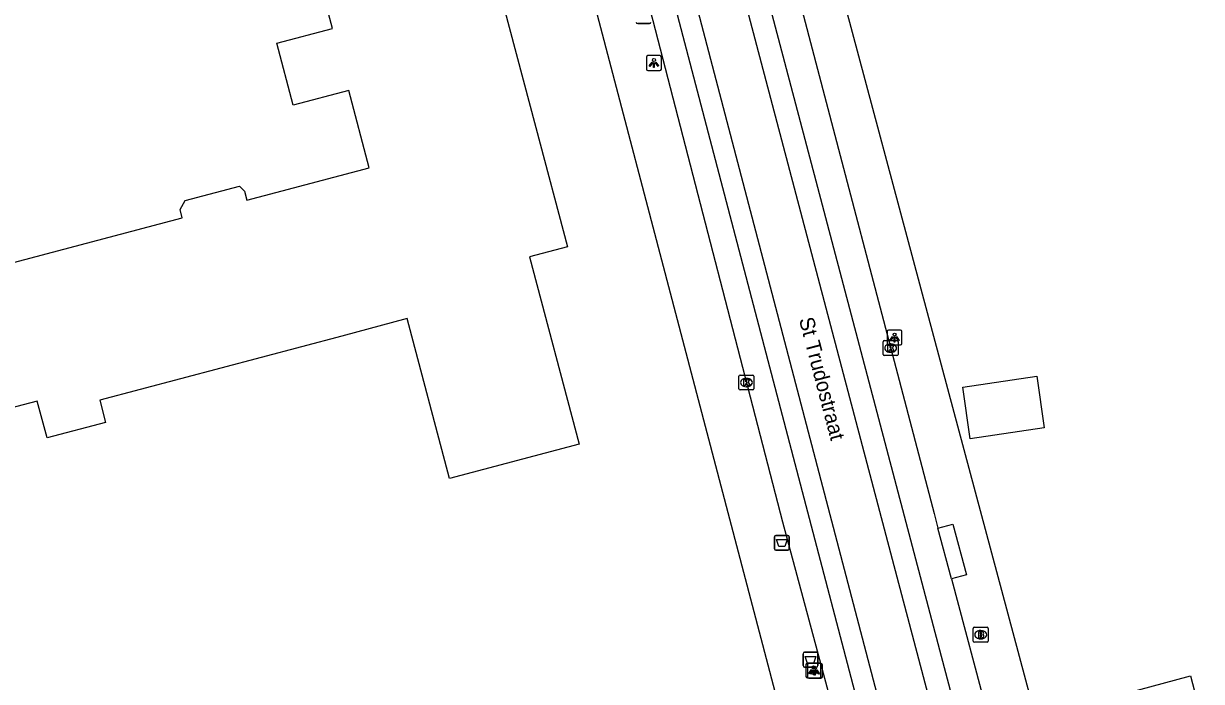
# Model space of a CAD drawing. Extents: x 159377 to 159983, y 382996 to 383595.
# Drawn here: x 159627.9 to 159706.9, y 383388.8 to 383433 of the extents above; entities that cross this region are included whole.
import ezdxf

# ---------------------------------------------------------------- set-up
doc = ezdxf.new("R2010")
doc.units = 0
for name, color, linetype in [('IMGEO_Afvalbak', 7, 'Continuous'), ('IMGEO_Brandkraan', 7, 'Continuous'), ('IMGEO_Kolk', 7, 'Continuous'), ('IMGEO_Lichtpunt', 7, 'Continuous'), ('IMGEO_Openbare_ruimte_label', 7, 'Continuous'), ('IMGEO_Pand', 7, 'Continuous'), ('IMGEO_Rijbaan_lokaal_gesloten', 7, 'Continuous'), ('IMGEO_Voetpad_open', 7, 'Continuous')]:
    doc.layers.add(name, color=color, linetype=linetype)

msp = doc.modelspace()

# ---------------------------------------------------------------- linework, layer by layer
at = {"layer": 'IMGEO_Afvalbak'}
for p, q in [((159669.861, 383432.991), (159669.071, 383432.991)), ((159669.071, 383432.991), (159669.861, 383432.991)), ((159678.253, 383397.748), (159678.253, 383398.548)), ((159678.253, 383398.548), (159678.253, 383397.748)), ((159678.353, 383398.648), (159679.143, 383398.648)), ((159679.143, 383398.648), (159678.353, 383398.648)), ((159679.243, 383398.548), (159679.243, 383397.748)), ((159679.243, 383397.748), (159679.243, 383398.548)), ((159679.143, 383397.648), (159678.353, 383397.648)), ((159678.353, 383397.648), (159679.143, 383397.648)), ((159680.176, 383389.909), (159680.176, 383390.709)), ((159680.176, 383390.709), (159680.176, 383389.909)), ((159680.276, 383390.809), (159681.066, 383390.809)), ((159681.066, 383390.809), (159680.276, 383390.809)), ((159681.166, 383390.709), (159681.166, 383389.909)), ((159681.166, 383389.909), (159681.166, 383390.709)), ((159681.066, 383389.809), (159680.276, 383389.809)), ((159680.276, 383389.809), (159681.066, 383389.809))]:
    msp.add_line(p, q, dxfattribs=at)
for points in [[(159678.396, 383398.362), (159679.1, 383398.362), (159678.951, 383397.892), (159678.545, 383397.892), (159678.396, 383398.362)], [(159680.319, 383390.523), (159681.023, 383390.523), (159680.874, 383390.053), (159680.468, 383390.053), (159680.319, 383390.523)]]:
    msp.add_lwpolyline(points, dxfattribs=at)
for centre, start, end in [((159669.071, 383433.091), 180, 270), ((159669.071, 383433.091), 180, 270), ((159669.861, 383433.091), 270, 0), ((159669.861, 383433.091), 270, 0), ((159678.353, 383398.548), 90, 180), ((159678.353, 383398.548), 90, 180), ((159679.143, 383398.548), 0, 90), ((159679.143, 383398.548), 360, 90), ((159678.353, 383397.748), 180, 270), ((159678.353, 383397.748), 180, 270), ((159679.143, 383397.748), 270, 0), ((159679.143, 383397.748), 270, 0), ((159680.276, 383390.709), 90, 180), ((159680.276, 383390.709), 90, 180), ((159681.066, 383390.709), 0, 90), ((159681.066, 383390.709), 360, 90), ((159680.276, 383389.909), 180, 270), ((159680.276, 383389.909), 180, 270), ((159681.066, 383389.909), 270, 0), ((159681.066, 383389.909), 270, 0)]:
    msp.add_arc(centre, 0.1, start, end, dxfattribs=at)
at = {"layer": 'IMGEO_Brandkraan'}
for p, q in [((159691.594, 383391.559), (159691.594, 383392.411)), ((159691.669, 383392.485), (159692.521, 383392.485)), ((159692.082, 383392.265), (159692.107, 383392.265)), ((159692.595, 383392.411), (159692.595, 383391.559)), ((159692.521, 383391.485), (159691.669, 383391.485)), ((159692.105, 383391.705), (159692.08, 383391.705))]:
    msp.add_line(p, q, dxfattribs=at)
for points in [[(159691.594, 383391.559), (159691.594, 383392.411)], [(159691.669, 383392.485), (159692.521, 383392.485)], [(159691.942, 383392.185), (159691.942, 383391.785), (159692.155, 383391.785)], [(159692.173, 383392.185), (159691.942, 383392.185)], [(159692.121, 383392.104), (159692.067, 383392.104), (159692.067, 383392.028)], [(159692.067, 383392.028), (159692.12, 383392.028)], [(159692.129, 383391.952), (159692.067, 383391.952), (159692.067, 383391.871)], [(159692.067, 383391.871), (159692.129, 383391.871)], [(159692.595, 383392.411), (159692.595, 383391.559)], [(159692.521, 383391.485), (159691.669, 383391.485)]]:
    msp.add_lwpolyline(points, dxfattribs=at)
for centre, radius, start, end in [((159691.671, 383392.409), 0.0765, 91.55205, 178.44795), ((159691.671, 383392.409), 0.0765, 91.55205, 178.44795), ((159692.122, 383392.066), 0.0379, 267.82845, 90.93552), ((159692.13, 383391.911), 0.0404, 269.87594, 90.50774), ((159692.161, 383392.036), 0.251, 268.66757, 293.53466), ((159692.177, 383392.04), 0.145, 59.4692, 91.53667), ((159692.202, 383392.087), 0.0922, 285.51372, 58.15012), ((159692.207, 383391.895), 0.105, 301.31148, 78.98903), ((159692.519, 383392.409), 0.0765, 1.55205, 88.44795), ((159692.519, 383392.409), 0.0765, 1.55205, 88.44795), ((159691.671, 383391.561), 0.0765, 181.55205, 268.44795), ((159691.671, 383391.561), 0.0765, 181.55205, 268.44795), ((159692.519, 383391.561), 0.0765, 271.55205, 358.44795), ((159692.519, 383391.561), 0.0765, 271.55205, 358.44795)]:
    msp.add_arc(centre, radius, start, end, dxfattribs=at)
for centre, major_axis, ratio, start_param, end_param in [((159692.081, 383391.985), (-0.387, 0.002), 0.722429, 4.712389, 7.853982), ((159692.106, 383391.985), (-0.39, 0.002), 0.717154, 1.570796, 4.712389)]:
    msp.add_ellipse(centre, major_axis=major_axis, ratio=ratio, start_param=start_param, end_param=end_param, dxfattribs=at)
at = {"layer": 'IMGEO_Kolk'}
for p, q in [((159685.548, 383410.789), (159685.548, 383411.641)), ((159685.623, 383411.715), (159686.475, 383411.715)), ((159686.036, 383411.495), (159686.061, 383411.495)), ((159686.549, 383411.641), (159686.549, 383410.789)), ((159686.475, 383410.715), (159685.623, 383410.715)), ((159686.059, 383410.935), (159686.034, 383410.935)), ((159675.871, 383408.48), (159675.871, 383409.332)), ((159675.946, 383409.406), (159676.798, 383409.406)), ((159676.359, 383409.186), (159676.384, 383409.186)), ((159676.872, 383409.332), (159676.872, 383408.48)), ((159676.798, 383408.406), (159675.946, 383408.406)), ((159676.382, 383408.626), (159676.357, 383408.626))]:
    msp.add_line(p, q, dxfattribs=at)
for points in [[(159685.548, 383410.789), (159685.548, 383411.641)], [(159685.623, 383411.715), (159686.475, 383411.715)], [(159686.549, 383411.641), (159686.549, 383410.789)], [(159686.475, 383410.715), (159685.623, 383410.715)], [(159685.869, 383411.415), (159685.992, 383411.415), (159685.992, 383411.264), (159686.122, 383411.415), (159686.286, 383411.415), (159686.14, 383411.264), (159686.293, 383411.015), (159686.141, 383411.015), (159686.056, 383411.179), (159685.992, 383411.112), (159685.992, 383411.015), (159685.869, 383411.015), (159685.869, 383411.415)], [(159675.871, 383408.48), (159675.871, 383409.332)], [(159675.946, 383409.406), (159676.798, 383409.406)], [(159676.192, 383409.106), (159676.315, 383409.106), (159676.315, 383408.955), (159676.445, 383409.106), (159676.609, 383409.106), (159676.463, 383408.955), (159676.616, 383408.706), (159676.464, 383408.706), (159676.379, 383408.87), (159676.315, 383408.803), (159676.315, 383408.706), (159676.192, 383408.706), (159676.192, 383409.106)], [(159676.872, 383409.332), (159676.872, 383408.48)], [(159676.798, 383408.406), (159675.946, 383408.406)]]:
    msp.add_lwpolyline(points, dxfattribs=at)
for centre, start, end in [((159685.625, 383411.639), 91.55205, 178.44795), ((159685.625, 383411.639), 91.55205, 178.44795), ((159686.473, 383411.639), 1.55205, 88.44795), ((159686.473, 383411.639), 1.55205, 88.44795), ((159685.625, 383410.791), 181.55205, 268.44795), ((159685.625, 383410.791), 181.55205, 268.44795), ((159686.473, 383410.791), 271.55205, 358.44795), ((159686.473, 383410.791), 271.55205, 358.44795), ((159675.948, 383409.33), 91.55205, 178.44795), ((159675.948, 383409.33), 91.55205, 178.44795), ((159676.796, 383409.33), 1.55205, 88.44795), ((159676.796, 383409.33), 1.55205, 88.44795), ((159675.948, 383408.482), 181.55205, 268.44795), ((159675.948, 383408.482), 181.55205, 268.44795), ((159676.796, 383408.482), 271.55205, 358.44795), ((159676.796, 383408.482), 271.55205, 358.44795)]:
    msp.add_arc(centre, 0.0765, start, end, dxfattribs=at)
for centre, major_axis, ratio, start_param, end_param in [((159686.035, 383411.215), (-0.387, 0.002), 0.722429, 4.712389, 7.853982), ((159686.06, 383411.215), (-0.39, 0.002), 0.717154, 1.570796, 4.712389), ((159676.358, 383408.906), (-0.387, 0.002), 0.722429, 4.712389, 7.853982), ((159676.383, 383408.906), (-0.39, 0.002), 0.717154, 1.570796, 4.712389)]:
    msp.add_ellipse(centre, major_axis=major_axis, ratio=ratio, start_param=start_param, end_param=end_param, dxfattribs=at)
at = {"layer": 'IMGEO_Lichtpunt'}
for p, q in [((159669.666, 383430.746), (159669.666, 383429.939)), ((159669.666, 383430.746), (159669.666, 383429.939)), ((159670.568, 383430.841), (159669.76, 383430.841)), ((159670.568, 383430.841), (159669.76, 383430.841)), ((159670.662, 383429.939), (159670.662, 383430.746)), ((159670.662, 383429.939), (159670.662, 383430.746)), ((159669.76, 383429.845), (159670.568, 383429.845)), ((159669.76, 383429.845), (159670.568, 383429.845)), ((159685.81, 383412.327), (159685.81, 383411.52)), ((159685.81, 383412.327), (159685.81, 383411.52)), ((159686.712, 383412.422), (159685.904, 383412.422)), ((159686.712, 383412.422), (159685.904, 383412.422)), ((159686.806, 383411.52), (159686.806, 383412.327)), ((159686.806, 383411.52), (159686.806, 383412.327)), ((159685.904, 383411.426), (159686.712, 383411.426)), ((159685.904, 383411.426), (159686.712, 383411.426)), ((159680.364, 383389.989), (159680.364, 383389.182)), ((159680.364, 383389.989), (159680.364, 383389.182)), ((159681.266, 383390.084), (159680.458, 383390.084)), ((159681.266, 383390.084), (159680.458, 383390.084)), ((159680.469, 383389.966), (159680.469, 383389.159)), ((159680.469, 383389.966), (159680.469, 383389.159)), ((159681.371, 383390.061), (159680.563, 383390.061)), ((159681.371, 383390.061), (159680.563, 383390.061)), ((159681.36, 383389.182), (159681.36, 383389.989)), ((159681.36, 383389.182), (159681.36, 383389.989)), ((159681.465, 383389.159), (159681.465, 383389.966)), ((159681.465, 383389.159), (159681.465, 383389.966)), ((159680.458, 383389.088), (159681.266, 383389.088)), ((159680.458, 383389.088), (159681.266, 383389.088)), ((159680.563, 383389.065), (159681.371, 383389.065)), ((159680.563, 383389.065), (159681.371, 383389.065))]:
    msp.add_line(p, q, dxfattribs=at)
for points in [[(159670.04, 383430.41), (159670.079, 383430.382), (159669.891, 383430.12), (159669.853, 383430.147), (159670.04, 383430.41)], [(159670.142, 383430.362), (159670.189, 383430.362), (159670.189, 383430.04), (159670.142, 383430.04), (159670.142, 383430.362)], [(159670.252, 383430.382), (159670.29, 383430.409), (159670.477, 383430.147), (159670.438, 383430.119), (159670.252, 383430.382)], [(159686.184, 383411.991), (159686.223, 383411.963), (159686.035, 383411.701), (159685.997, 383411.728), (159686.184, 383411.991)], [(159686.286, 383411.943), (159686.333, 383411.943), (159686.333, 383411.621), (159686.286, 383411.621), (159686.286, 383411.943)], [(159686.396, 383411.963), (159686.434, 383411.99), (159686.621, 383411.728), (159686.582, 383411.7), (159686.396, 383411.963)], [(159680.738, 383389.653), (159680.777, 383389.625), (159680.589, 383389.363), (159680.551, 383389.39), (159680.738, 383389.653)], [(159680.843, 383389.63), (159680.882, 383389.602), (159680.694, 383389.34), (159680.656, 383389.367), (159680.843, 383389.63)], [(159680.84, 383389.605), (159680.887, 383389.605), (159680.887, 383389.283), (159680.84, 383389.283), (159680.84, 383389.605)], [(159680.945, 383389.582), (159680.992, 383389.582), (159680.992, 383389.26), (159680.945, 383389.26), (159680.945, 383389.582)], [(159680.95, 383389.625), (159680.988, 383389.652), (159681.175, 383389.39), (159681.136, 383389.362), (159680.95, 383389.625)], [(159681.055, 383389.602), (159681.093, 383389.629), (159681.28, 383389.367), (159681.241, 383389.339), (159681.055, 383389.602)]]:
    msp.add_lwpolyline(points, dxfattribs=at)
for centre in [(159670.165, 383430.544), (159686.309, 383412.125), (159680.863, 383389.787), (159680.968, 383389.764)]:
    msp.add_circle(centre, 0.0994, dxfattribs=at)
for centre, start, end in [((159669.76, 383430.746), 90, 180), ((159669.76, 383430.746), 90, 180), ((159670.568, 383430.746), 0, 90), ((159670.568, 383430.746), 0, 90), ((159669.76, 383429.939), 180, 270), ((159669.76, 383429.939), 180, 270), ((159670.568, 383429.939), 270, 0), ((159670.568, 383429.939), 270, 360), ((159685.904, 383412.327), 90, 180), ((159685.904, 383412.327), 90, 180), ((159686.712, 383412.327), 0, 90), ((159686.712, 383412.327), 0, 90), ((159685.904, 383411.52), 180, 270), ((159685.904, 383411.52), 180, 270), ((159686.712, 383411.52), 270, 0), ((159686.712, 383411.52), 270, 360), ((159680.458, 383389.989), 90, 180), ((159680.458, 383389.989), 90, 180), ((159680.563, 383389.966), 90, 180), ((159680.563, 383389.966), 90, 180), ((159681.266, 383389.989), 0, 90), ((159681.266, 383389.989), 0, 90), ((159681.371, 383389.966), 0, 90), ((159681.371, 383389.966), 0, 90), ((159680.458, 383389.182), 180, 270), ((159680.458, 383389.182), 180, 270), ((159680.563, 383389.159), 180, 270), ((159680.563, 383389.159), 180, 270), ((159681.266, 383389.182), 270, 0), ((159681.266, 383389.182), 270, 360), ((159681.371, 383389.159), 270, 0), ((159681.371, 383389.159), 270, 360)]:
    msp.add_arc(centre, 0.0946, start, end, dxfattribs=at)
at = {"layer": 'IMGEO_Pand'}
for points in [[(159644.241, 383456.678), (159645.061, 383454.536), (159648.029, 383455.323), (159652.132, 383456.411), (159653.676, 383452.21), (159654.24, 383452.36), (159655.17, 383448.855), (159656.117, 383449.106), (159662.242, 383426.01), (159664.362, 383418.013), (159661.82, 383417.339), (159665.152, 383404.773), (159656.453, 383402.466), (159653.608, 383413.193), (159649.208, 383412.027), (159632.973, 383407.721), (159633.367, 383406.233), (159629.434, 383405.19), (159628.777, 383407.665), (159625.924, 383406.909)], [(159626.428, 383416.757), (159638.506, 383419.96), (159638.36, 383420.511), (159638.714, 383421.12), (159642.351, 383422.085), (159642.69, 383421.743), (159642.852, 383421.135), (159651.059, 383423.312), (159649.68, 383428.511), (159645.951, 383427.522), (159644.852, 383431.666), (159648.59, 383432.657), (159644.994, 383446.217), (159645.974, 383446.477), (159645.138, 383449.628), (159636.574, 383447.356), (159635.631, 383449.797), (159623.624, 383445.114)], [(159695.852, 383409.334), (159696.362, 383405.865), (159691.394, 383405.135), (159690.884, 383408.604), (159695.852, 383409.334)], [(159695.793, 383386.432), (159700.622, 383387.732), (159703.447, 383388.493), (159706.168, 383389.226), (159706.561, 383387.767), (159706.838, 383386.738), (159704.111, 383386.004), (159705.003, 383382.691)]]:
    msp.add_lwpolyline(points, dxfattribs=at)
at = {"layer": 'IMGEO_Rijbaan_lokaal_gesloten'}
for points in [[(159706.907, 383324.871), (159703.844, 383336.06), (159696.414, 383364.212), (159689.359, 383390.944), (159681.054, 383422.407), (159675.902, 383441.929), (159673.093, 383452.571), (159671.587, 383458.28)], [(159670.094, 383457.885), (159670.625, 383455.872), (159678.409, 383426.38), (159686.465, 383395.857), (159692.786, 383371.909), (159698.534, 383350.133), (159705.315, 383324.44), (159706.001, 383324.626), (159706.907, 383324.871)], [(159700.731, 383323.191), (159691.898, 383356.687), (159665.691, 383456.728)], [(159700.731, 383323.191), (159702.049, 383323.57), (159696.447, 383345.036), (159693.274, 383357.013), (159667.185, 383456.552), (159667.027, 383457.076)]]:
    msp.add_lwpolyline(points, dxfattribs=at)
at = {"layer": 'IMGEO_Voetpad_open'}
for points in [[(159695.793, 383386.432), (159689.89, 383408.493), (159681.184, 383441.029), (159670.697, 383478.285), (159669.551, 383482.179), (159664.244, 383500), (159658.841, 383518.144)], [(159678.304, 383388.157), (159659.581, 383459.485), (159659.066, 383461.404)], [(159673.465, 383458.741), (159673.929, 383456.929), (159674.718, 383453.996), (159679.139, 383437.543), (159688.963, 383400.109), (159689.221, 383399.138)], [(159663.864, 383456.282), (159664.964, 383452.218), (159665.106, 383451.555), (159670.1, 383433.187), (159678.787, 383399.561), (159682.877, 383384.322), (159688.475, 383363.216), (159690.31, 383356.311), (159696.363, 383333.532), (159698.5, 383325.536), (159698.524, 383325.331)], [(159689.221, 383399.138), (159690.226, 383399.406), (159691.133, 383395.999), (159690.128, 383395.731)], [(159690.128, 383395.731), (159689.221, 383399.138)], [(159690.128, 383395.731), (159695.004, 383377.404), (159700.034, 383358.613), (159702.961, 383347.681), (159705.825, 383336.598), (159706.48, 383334.224)]]:
    msp.add_lwpolyline(points, dxfattribs=at)

# ---------------------------------------------------------------- texts
at = {"layer": 'IMGEO_Openbare_ruimte_label'}
msp.add_text('St Trudostraat', height=1, rotation=284.71731, dxfattribs=at).set_placement((159679.888, 383413.147))

doc.saveas('drawing.dxf')
